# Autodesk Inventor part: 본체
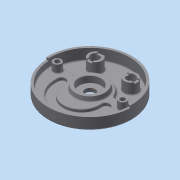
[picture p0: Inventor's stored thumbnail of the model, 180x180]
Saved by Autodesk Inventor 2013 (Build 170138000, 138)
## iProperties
Created: 2015-04
Part Number: 본체
Material: 일반
Document SubType Name: Modeling
Designer: Administrator
Density: 1 g/cm^3
Author: Administrator
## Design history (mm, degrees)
sketch "스케치1"
  geometry: C1 r 95 at (0, 0); 1 further point
  constraints: 1 centre point, 1 coincident
  dimensions: "d0" = 190 diameter of C1
extrude "돌출1" new body sketch "스케치1" distance "d1" = 32; taper "d2" = 0 deg
sketch "스케치2"
  geometry: C1 r 95 at (0, 0) reference; C2 r 90 at (0, 0)
  constraints: 1 centre point, 1 coincident
  dimensions: "d3" = 180 diameter of C2
extrude "돌출2" cut sketch "스케치2" distance "d4" = 25; taper "d5" = 0 deg
sketch "스케치3"
  geometry: L1 (-101.472, 0)-(101.472, 0); L2 (-94.916, -4)-(-89.929, -3.564); L3 (89.951, -2.955)-(94.939, -3.391); C1 r 90 at (0, 0) reference; A1 r 95 centre (0, 0) between (-95, 0) and (95, 0); A2 r 90 centre (0, 0) between (-90, 0) and (90, 0); 1 further point
  constraints: 8 point on circle, 6 end point, 4 point on line, 3 coincident, 2 centre point, 1 horizontal, 1 midpoint
  dimensions: "d6" = 5 deg angle of L2 L1; "d7" = 190 diameter of A1; "d8" = 180 diameter of A2; "d9" = 4.98634 horizontal distance of L2.start L2.end; "d10" = 5 deg angle of L1 L3; "d11" = 4.98797 horizontal distance of L3.start L3.end
extrude "돌출3" cut sketch "스케치3" distance "d12" = 5; taper "d13" = 0 deg
node "작업 평면1"
sketch "스케치9"
  geometry: C1 r 15 at (-40, 52); C2 r 15 at (40, 52); 1 further point
  constraints: 2 centre point, 1 horizontal alignment
  dimensions: "d77" = 30 diameter of C1; "d78" = 30 diameter of C2; "d79" = 80 distance of C2.centre C1.centre; "d80" = 40 horizontal distance of point (0, 0) C1.centre; "d81" = 52 vertical distance of point (0, 0) C1.centre
extrude "돌출7" join sketch "스케치9" stored distance "d82" = 25; taper "d83" = 0 deg
sketch "스케치10"
  geometry: C1 r 15 at (0, 0) reference; C2 r 15 at (80, 0) reference; C3 r 10 at (0, 0); C4 r 10 at (80, 0); 1 further point
  constraints: 2 centre point, 2 coincident
  dimensions: "d84" = 20 diameter of C3; "d85" = 20 diameter of C4
extrude "돌출8" cut sketch "스케치10" stored distance "d86" = 25; taper "d87" = 0 deg
sketch "스케치11"
  geometry: L1 (-6, 19.341)-(6, 19.341); L2 (6, 19.341)-(6, -18.609); L3 (6, -18.609)-(-6, -18.609); L4 (-6, -18.609)-(-6, 19.341); L5 (59.177, 6)-(102.733, 6); L6 (102.733, 6)-(102.733, -6); L7 (102.733, -6)-(59.177, -6); L8 (59.177, -6)-(59.177, 6); C1 r 10 at (0, 0) reference; C2 r 10 at (80, 0) reference; C3 r 15 at (80, 0) reference; 3 further points
  constraints: 16 end point, 4 parallel, 2 horizontal, 2 midpoint, 2 perpendicular, 1 horizontal alignment, 1 vertical alignment
  dimensions: "d88" = 12 distance of L1.start L1.end; "d90" = 12 distance of L7.end L5.start
extrude "돌출9" cut sketch "스케치11" distance "d92" = 3; taper "d93" = 0 deg
sketch "스케치12"
  geometry: L1 (-89.196, 12)-(-40.249, 12); L2 (40.249, 12)-(89.196, 12); A1 r 90 centre (0, 0) between (-89.196, 12) and (89.196, 12) reference; A2 r 42 centre (0, 0) between (40.249, 12) and (-40.249, 12); A3 r 90 centre (0, 0) between (-89.196, 12) and (89.196, 12)
  constraints: 6 point on circle, 4 end point, 2 centre point, 2 coincident, 2 horizontal, 1 horizontal alignment
  dimensions: "d98" = 12 distance from line of A1.centre L2; "d100" = 42 radius of A2
extrude "돌출10" join sketch "스케치12" distance "d101" = 7; taper "d102" = 0 deg
sketch "스케치13"
  geometry: A1 r 90 centre (0, 0) between (-89.196, 12) and (89.196, 12) reference; A2 r 59 centre (0, -19) between (-58.704, -13.1) and (58.704, -13.1); A3 r 41 centre (0, -19) between (-40.794, -14.9) and (40.794, -14.9); A4 r 9 centre (-49.749, -14) between (-40.794, -14.9) and (-58.704, -13.1); A5 r 9 centre (49.749, -14) between (58.704, -13.1) and (40.794, -14.9)
  constraints: 8 point on circle, 4 centre point, 2 tangent, 1 coincident, 1 horizontal alignment, 1 vertical alignment
  dimensions: "d103" = 118 diameter of A2; "d104" = 19 distance of A2.centre A1.centre; "d105" = 82 diameter of A3; "d106" = 18 diameter of A4; "d107" = 18 diameter of A5; "d108" = 5 vertical distance of A4.centre A3.centre
extrude "돌출11" cut sketch "스케치13" distance "d109" = 7; taper "d110" = 0 deg
sketch "스케치14"
  geometry: C1 r 9 at (-74, 0); C2 r 9 at (74, 0); A1 r 90 centre (0, 0) between (-89.196, 12) and (89.196, 12) reference
  constraints: 2 centre point, 2 horizontal alignment
  dimensions: "d111" = 18 diameter of C1; "d112" = 18 diameter of C2; "d113" = 148 distance of C2.centre C1.centre; "d114" = 74 distance of A1.centre C1.centre
extrude "돌출12" join sketch "스케치14" stored distance "d115" = 7; taper "d116" = 0 deg
sketch "스케치15"
  geometry: C1 r 9 at (-74, 0) reference; C2 r 9 at (74, 0) reference; 2 further points
  constraints: 2 coincident
hole "구멍5" sketch "스케치15" at (-74, 0), (74, 0) diameter "d117" = 11; stored, may be unused: countersink angle "d121" = 90 deg, drill point angle "d123" = 0 deg; dims "d118" = 6, "d119" = 18, "d120" = 11, "d122" = 11
sketch "스케치16"
  geometry: C1 r 35 at (0, 0); A1 r 42 centre (0, 0) between (40.249, 12) and (-40.249, 12) reference
  constraints: 1 centre point, 1 coincident
  dimensions: "d124" = 70 diameter of C1
extrude "돌출13" join sketch "스케치16" distance "d125" = 10; taper "d126" = -10 deg
hole "구멍6" diameter "d129" = 23; stored, may be unused: countersink angle "d133" = 90 deg, drill point angle "d135" = 0 deg; dims "d127" = 10, "d128" = 10, "d130" = 6, "d131" = 50, "d132" = 15, "d134" = 11
fillet "모깎기4" dims "d136" = 10
fillet "모깎기5" dims "d137" = 3, "d159" = 1
chamfer "모따기1" distance "d138" = 1; stored, may be unused: second distance "d139" = 2, angle "d140" = 45 deg
sketch "스케치17"
  geometry: L1 (-40, 0)-(43.953, 0); L2 (-36.062, -36.062)-(-52.326, -52.326); L3 (36.062, -36.062)-(52.326, -52.326); C1 r 12.5 at (0, 0) reference; A1 r 51 centre (0, 0) between (-36.062, -36.062) and (36.062, -36.062); A2 r 74 centre (0, 0) between (-52.326, -52.326) and (52.326, -52.326)
  constraints: 6 end point, 4 point on circle, 2 centre point, 2 coincident, 1 horizontal
  dimensions: "d141" = 102 diameter of A1; "d145" = 74 radius of A2; "d146" = 45 deg angle of L2 L1; "d147" = 45 deg angle of L3 L1; "d148" = 23 distance of L3.start L3.end; "d149" = 23 distance of L2.start L2.end
extrude "돌출14" join sketch "스케치17" distance "d150" = 5.5; taper "d151" = 0 deg
fillet "모깎기6" dims "d152" = 5
fillet "모깎기7" dims "d153" = 3
sketch "스케치18"
  geometry: C1 r 68 at (0, 0); A1 r 71 centre (0, 0) between (-46.435, -53.711) and (46.435, -53.711) reference
  constraints: 1 centre point, 1 coincident, 1 other
  dimensions: "d154" = 136 diameter of C1
feature "엠보싱1" sketch "스케치18" dims "d1" = 32, "d2" = 0, "d155" = 0.5, "d156" = 0
fillet "모깎기8" dims "d157" = 5
fillet "모깎기9" dims "d158" = 3
chamfer "모따기2" distance "d160" = 1; stored, may be unused: second distance "d161" = 2, angle "d162" = 45 deg
fillet "모깎기10" dims "d163" = 0.3
node "솔리드1"
node "투영된 루프1"
node "투영된 루프2"
other parameters: "d15" = 12, "d23" = 118, "d76" = 0, "d97" = 12, "d142" = 148, "d143" = 90 deg, "d144" = 45 deg
